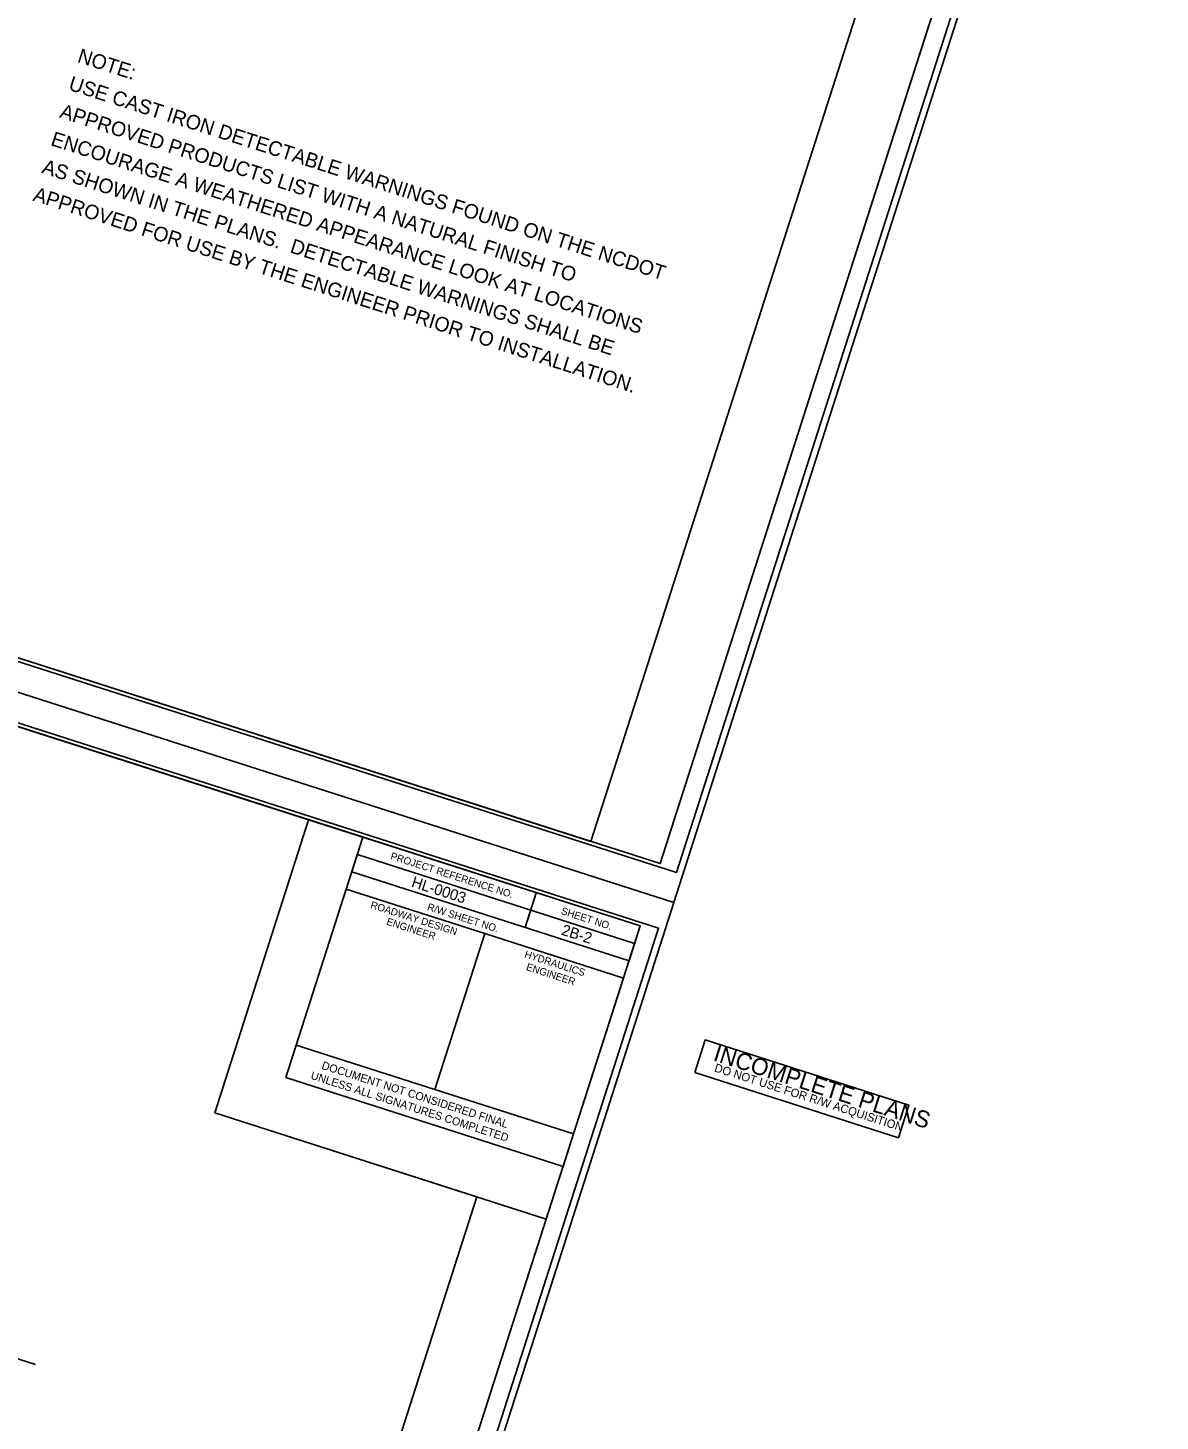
# Model space of a CAD drawing. Extents: x 928111 to 937215, y 684320 to 686530.
# Drawn here: x 933670.73 to 933701.85, y 684674.31 to 684712.61 of the extents above; entities that cross this region are included whole.
import ezdxf

# ---------------------------------------------------------------- set-up
doc = ezdxf.new("R2010")
doc.units = 0
for name, color, linetype in [('Exist Roads EOP', 7, 'Continuous'), ('Prop DSN Text', 7, 'Continuous'), ('Sheet Clip Boundary CELL', 7, 'Continuous'), ('Sheet Cutting Line CELL', 7, 'Continuous'), ('Sheet Data Field CELL', 7, 'Continuous'), ('Sheet Layout Plan Border', 7, 'Continuous'), ('Sheet Plan CELL', 7, 'Continuous'), ('Sheet Plan Layout CELL', 7, 'Continuous'), ('Sheet Plot Border Inside CELL', 7, 'Continuous'), ('Sheet Plot Border Outside CELL', 7, 'Continuous'), ('Sheet Sticker Exception Certification CELL', 7, 'Continuous'), ('Sheet Sticker Incomplete CELL', 7, 'Continuous')]:
    doc.layers.add(name, color=color, linetype=linetype)

msp = doc.modelspace()

# ---------------------------------------------------------------- linework, layer by layer
at = {"layer": 'Exist Roads EOP'}
msp.add_line((933654.351, 684681.184), (933670.933, 684675.868), dxfattribs=at)
at = {"layer": 'Sheet Clip Boundary CELL'}
for points in [[(933632.873, 684707.339), (933686.201, 684690.246), (933696.439, 684722.185), (933689.23, 684724.496), (933691.812, 684732.552), (933645.693, 684747.335)], [(933619.504, 684665.63), (933672.831, 684648.536), (933683.069, 684680.476), (933675.86, 684682.787), (933678.442, 684690.842), (933632.324, 684705.625)]]:
    msp.add_lwpolyline(points, close=True, dxfattribs=at)
at = {"layer": 'Sheet Cutting Line CELL'}
for p, q in [((933624.352, 684709.125), (933688.478, 684688.57)), ((933688.478, 684688.57), (933624.352, 684709.125))]:
    msp.add_line(p, q, dxfattribs=at)
at = {"layer": 'Sheet Layout Plan Border'}
for points in [[(933632.873, 684707.339), (933686.201, 684690.246), (933696.439, 684722.185), (933689.23, 684724.496), (933691.812, 684732.552), (933645.693, 684747.335)], [(933619.504, 684665.63), (933672.831, 684648.536), (933683.069, 684680.476), (933675.86, 684682.787), (933678.442, 684690.842), (933632.324, 684705.625)]]:
    msp.add_lwpolyline(points, close=True, dxfattribs=at)
at = {"layer": 'Sheet Plan CELL'}
for p, q in [((933679.782, 684689.886), (933687.402, 684687.443)), ((933679.63, 684689.409), (933679.477, 684688.933)), ((933679.63, 684689.409), (933687.25, 684686.967)), ((933679.63, 684689.409), (933687.25, 684686.967)), ((933684.697, 684688.835), (933684.394, 684687.882)), ((933683.288, 684687.711), (933681.916, 684683.427))]:
    msp.add_line(p, q, dxfattribs=at)
for points in [[(933700.927, 684729.63), (933643.789, 684747.945), (933630.969, 684707.95), (933688.106, 684689.635)], [(933630.969, 684707.95), (933643.787, 684747.945), (933693.306, 684732.074), (933691.474, 684726.358), (933699.093, 684723.915), (933688.106, 684689.635)], [(933687.557, 684687.921), (933630.419, 684706.236), (933617.599, 684666.24), (933674.736, 684647.926)], [(933617.599, 684666.24), (933630.418, 684706.235), (933679.936, 684690.364), (933678.104, 684684.648), (933685.724, 684682.205), (933674.736, 684647.926)], [(933679.936, 684690.364), (933687.557, 684687.921), (933687.25, 684686.967), (933679.63, 684689.409)], [(933679.477, 684688.933), (933683.288, 684687.711), (933681.915, 684683.426), (933678.104, 684684.648)], [(933683.288, 684687.711), (933687.097, 684686.491), (933685.724, 684682.205), (933681.915, 684683.426)]]:
    msp.add_lwpolyline(points, close=True, dxfattribs=at)
at = {"layer": 'Sheet Plan Layout CELL'}
for points in [[(933643.787, 684747.945), (933630.969, 684707.95), (933688.105, 684689.635), (933698.343, 684721.575), (933689.23, 684724.496), (933691.812, 684732.552)], [(933630.418, 684706.235), (933617.599, 684666.24), (933674.736, 684647.926), (933684.973, 684679.865), (933675.86, 684682.787), (933678.442, 684690.842)], [(933675.86, 684682.787), (933684.974, 684679.865), (933687.558, 684687.921), (933678.442, 684690.842)]]:
    msp.add_lwpolyline(points, close=True, dxfattribs=at)
at = {"layer": 'Sheet Plot Border Inside CELL'}
for points in [[(933625.091, 684709.728), (933688.551, 684689.388), (933701.432, 684729.573), (933637.973, 684749.914)], [(933611.722, 684668.018), (933675.181, 684647.678), (933688.063, 684687.863), (933624.603, 684708.204)]]:
    msp.add_lwpolyline(points, close=True, dxfattribs=at)
at = {"layer": 'Sheet Plot Border Outside CELL'}
for points in [[(933624.352, 684709.125), (933688.478, 684688.57), (933701.848, 684730.28), (933637.722, 684750.835)], [(933610.982, 684667.415), (933675.109, 684646.86), (933688.478, 684688.57), (933624.352, 684709.125)]]:
    msp.add_lwpolyline(points, close=True, dxfattribs=at)
at = {"layer": 'Sheet Sticker Exception Certification CELL'}
for p, q in [((933677.817, 684683.753), (933678.104, 684684.648)), ((933677.817, 684683.753), (933678.104, 684684.648)), ((933678.104, 684684.648), (933685.724, 684682.206)), ((933678.104, 684684.648), (933685.724, 684682.206)), ((933685.437, 684681.31), (933677.817, 684683.753)), ((933685.437, 684681.31), (933677.817, 684683.753)), ((933685.724, 684682.205), (933685.437, 684681.31)), ((933685.724, 684682.205), (933685.437, 684681.31))]:
    msp.add_line(p, q, dxfattribs=at)
at = {"layer": 'Sheet Sticker Incomplete CELL'}
msp.add_lwpolyline([(933689.054, 684683.895), (933689.341, 684684.79), (933694.941, 684682.995), (933694.654, 684682.1)], close=True, dxfattribs=at)

# ---------------------------------------------------------------- texts
at = {"layer": 'Prop DSN Text'}
for s, p in [('NOTE:', (933672.062, 684711.676)), ('USE CAST IRON DETECTABLE WARNINGS FOUND ON THE NCDOT ', (933671.818, 684710.915)), ('APPROVED PRODUCTS LIST WITH A NATURAL FINISH TO ', (933671.574, 684710.153)), ('ENCOURAGE A WEATHERED APPEARANCE LOOK AT LOCATIONS ', (933671.329, 684709.391)), ('AS SHOWN IN THE PLANS.  DETECTABLE WARNINGS SHALL BE ', (933671.085, 684708.629)), ('APPROVED FOR USE BY THE ENGINEER PRIOR TO INSTALLATION.', (933670.841, 684707.867))]:
    msp.add_text(s, height=0.4, rotation=342.2273, dxfattribs=at).set_placement(p)
at = {"layer": 'Sheet Data Field CELL'}
for s, p in [('HL-0003', (933681.247, 684689.006)), ('2B-2', (933685.369, 684687.688))]:
    msp.add_text(s, height=0.3, rotation=342.2273, dxfattribs=at).set_placement(p)
at = {"layer": 'Sheet Plan CELL'}
for s, p in [('PROJECT REFERENCE NO.', (933680.675, 684689.761)), ('ROADWAY DESIGN', (933680.126, 684688.418)), ('R/W SHEET NO.', (933681.689, 684688.363)), ('SHEET NO.', (933685.365, 684688.253)), ('ENGINEER', (933680.567, 684687.96)), ('HYDRAULICS', (933684.36, 684687.062)), ('ENGINEER', (933684.406, 684686.713))]:
    msp.add_text(s, height=0.2, rotation=342.2273, dxfattribs=at).set_placement(p)
at = {"layer": 'Sheet Sticker Exception Certification CELL'}
for s, p in [('DOCUMENT NOT CONSIDERED FINAL', (933678.781, 684683.997)), ('DOCUMENT NOT CONSIDERED FINAL', (933678.781, 684683.997)), ('UNLESS ALL SIGNATURES COMPLETED', (933678.48, 684683.723)), ('UNLESS ALL SIGNATURES COMPLETED', (933678.48, 684683.723))]:
    msp.add_text(s, height=0.22, rotation=342.2273, dxfattribs=at).set_placement(p)
at = {"layer": 'Sheet Sticker Incomplete CELL'}
for s, height, p in [('INCOMPLETE PLANS', 0.4608, (933689.538, 684684.231)), ('DO NOT USE FOR R/W ACQUISITION', 0.2304, (933689.577, 684683.927))]:
    msp.add_text(s, height=height, rotation=342.2273, dxfattribs=at).set_placement(p)

doc.saveas('drawing.dxf')
